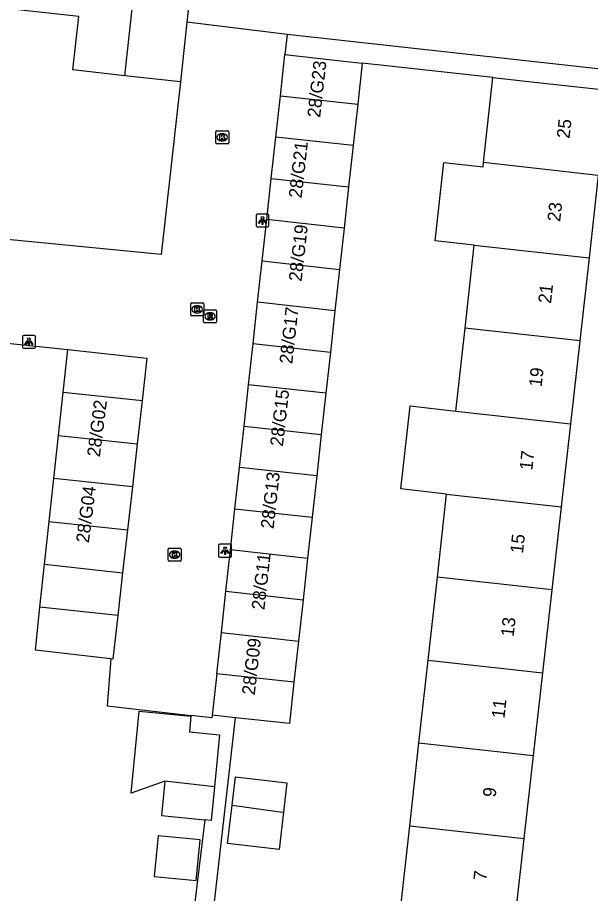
# Model space of a CAD drawing. Extents: x 162026 to 163499, y 387297 to 388169.
# Drawn here: x 162203.9 to 162248.1, y 387569 to 387636.4 of the extents above; entities that cross this region are included whole.
import ezdxf

# ---------------------------------------------------------------- set-up
doc = ezdxf.new("R2010")
doc.units = 0
for name, color, linetype in [('IMGEO_Kolk', 7, 'Continuous'), ('IMGEO_Lichtpunt', 7, 'Continuous'), ('IMGEO_Muur', 7, 'Continuous'), ('IMGEO_Pand', 7, 'Continuous'), ('IMGEO_Pand_nummerreeks', 7, 'Continuous'), ('IMGEO_Rijbaan_lokaal_open', 7, 'Continuous'), ('IMGEO_Rioolput', 7, 'Continuous'), ('IMGEO_Voetpad_open', 7, 'Continuous')]:
    doc.layers.add(name, color=color, linetype=linetype)

msp = doc.modelspace()

# ---------------------------------------------------------------- linework, layer by layer
at = {"layer": 'IMGEO_Kolk'}
for p, q in [((162219.264, 387627.682), (162220.116, 387627.682)), ((162219.189, 387626.756), (162219.189, 387627.608)), ((162219.677, 387627.462), (162219.702, 387627.462)), ((162220.19, 387627.608), (162220.19, 387626.756)), ((162220.116, 387626.682), (162219.264, 387626.682)), ((162219.7, 387626.902), (162219.675, 387626.902)), ((162217.264, 387613.502), (162217.264, 387614.354)), ((162217.339, 387614.428), (162218.191, 387614.428)), ((162217.752, 387614.208), (162217.777, 387614.208)), ((162218.265, 387614.354), (162218.265, 387613.502)), ((162217.775, 387613.648), (162217.75, 387613.648)), ((162218.191, 387613.428), (162217.339, 387613.428)), ((162215.53, 387594.615), (162215.53, 387595.467)), ((162215.605, 387595.541), (162216.457, 387595.541)), ((162216.018, 387595.321), (162216.043, 387595.321)), ((162216.531, 387595.467), (162216.531, 387594.615)), ((162216.041, 387594.761), (162216.016, 387594.761)), ((162216.457, 387594.541), (162215.605, 387594.541))]:
    msp.add_line(p, q, dxfattribs=at)
for points in [[(162219.264, 387627.682), (162220.116, 387627.682)], [(162219.189, 387626.756), (162219.189, 387627.608)], [(162219.51, 387627.382), (162219.633, 387627.382), (162219.633, 387627.231), (162219.763, 387627.382), (162219.927, 387627.382), (162219.781, 387627.231), (162219.934, 387626.982), (162219.782, 387626.982), (162219.697, 387627.146), (162219.633, 387627.079), (162219.633, 387626.982), (162219.51, 387626.982), (162219.51, 387627.382)], [(162220.19, 387627.608), (162220.19, 387626.756)], [(162220.116, 387626.682), (162219.264, 387626.682)], [(162217.264, 387613.502), (162217.264, 387614.354)], [(162217.339, 387614.428), (162218.191, 387614.428)], [(162218.265, 387614.354), (162218.265, 387613.502)], [(162217.585, 387614.128), (162217.708, 387614.128), (162217.708, 387613.977), (162217.838, 387614.128), (162218.002, 387614.128), (162217.856, 387613.977), (162218.009, 387613.728), (162217.857, 387613.728), (162217.772, 387613.892), (162217.708, 387613.825), (162217.708, 387613.728), (162217.585, 387613.728), (162217.585, 387614.128)], [(162218.191, 387613.428), (162217.339, 387613.428)], [(162215.53, 387594.615), (162215.53, 387595.467)], [(162215.605, 387595.541), (162216.457, 387595.541)], [(162216.531, 387595.467), (162216.531, 387594.615)], [(162215.851, 387595.241), (162215.974, 387595.241), (162215.974, 387595.09), (162216.104, 387595.241), (162216.268, 387595.241), (162216.122, 387595.09), (162216.275, 387594.841), (162216.123, 387594.841), (162216.038, 387595.005), (162215.974, 387594.938), (162215.974, 387594.841), (162215.851, 387594.841), (162215.851, 387595.241)], [(162216.457, 387594.541), (162215.605, 387594.541)]]:
    msp.add_lwpolyline(points, dxfattribs=at)
for centre, start, end in [((162219.266, 387627.606), 91.55205, 178.44795), ((162219.266, 387627.606), 91.55205, 178.44795), ((162220.114, 387627.606), 1.55205, 88.44795), ((162220.114, 387627.606), 1.55205, 88.44795), ((162219.266, 387626.758), 181.55205, 268.44795), ((162219.266, 387626.758), 181.55205, 268.44795), ((162220.114, 387626.758), 271.55205, 358.44795), ((162220.114, 387626.758), 271.55205, 358.44795), ((162217.341, 387614.352), 91.55205, 178.44795), ((162217.341, 387614.352), 91.55205, 178.44795), ((162218.189, 387614.352), 1.55205, 88.44795), ((162218.189, 387614.352), 1.55205, 88.44795), ((162217.341, 387613.504), 181.55205, 268.44795), ((162217.341, 387613.504), 181.55205, 268.44795), ((162218.189, 387613.504), 271.55205, 358.44795), ((162218.189, 387613.504), 271.55205, 358.44795), ((162215.607, 387595.465), 91.55205, 178.44795), ((162215.607, 387595.465), 91.55205, 178.44795), ((162216.455, 387595.465), 1.55205, 88.44795), ((162216.455, 387595.465), 1.55205, 88.44795), ((162215.607, 387594.617), 181.55205, 268.44795), ((162215.607, 387594.617), 181.55205, 268.44795), ((162216.455, 387594.617), 271.55205, 358.44795), ((162216.455, 387594.617), 271.55205, 358.44795)]:
    msp.add_arc(centre, 0.0765, start, end, dxfattribs=at)
for centre, major_axis, ratio, start_param, end_param in [((162219.676, 387627.182), (-0.387, 0.002), 0.722429, 4.712389, 7.853982), ((162219.701, 387627.182), (-0.39, 0.002), 0.717154, 1.570796, 4.712389), ((162217.751, 387613.928), (-0.387, 0.002), 0.722429, 4.712389, 7.853982), ((162217.776, 387613.928), (-0.39, 0.002), 0.717154, 1.570796, 4.712389), ((162216.017, 387595.041), (-0.387, 0.002), 0.722429, 4.712389, 7.853982), ((162216.042, 387595.041), (-0.39, 0.002), 0.717154, 1.570796, 4.712389)]:
    msp.add_ellipse(centre, major_axis=major_axis, ratio=ratio, start_param=start_param, end_param=end_param, dxfattribs=at)
at = {"layer": 'IMGEO_Lichtpunt'}
for p, q in [((162222.296, 387621.175), (162222.296, 387620.368)), ((162222.296, 387621.175), (162222.296, 387620.368)), ((162223.198, 387621.27), (162222.39, 387621.27)), ((162223.198, 387621.27), (162222.39, 387621.27)), ((162223.292, 387620.368), (162223.292, 387621.175)), ((162223.292, 387620.368), (162223.292, 387621.175)), ((162222.39, 387620.274), (162223.198, 387620.274)), ((162222.39, 387620.274), (162223.198, 387620.274)), ((162204.309, 387611.835), (162204.309, 387611.028)), ((162204.309, 387611.835), (162204.309, 387611.028)), ((162205.211, 387611.93), (162204.403, 387611.93)), ((162205.211, 387611.93), (162204.403, 387611.93)), ((162205.305, 387611.028), (162205.305, 387611.835)), ((162205.305, 387611.028), (162205.305, 387611.835)), ((162204.403, 387610.934), (162205.211, 387610.934)), ((162204.403, 387610.934), (162205.211, 387610.934)), ((162219.411, 387595.757), (162219.411, 387594.95)), ((162219.411, 387595.757), (162219.411, 387594.95)), ((162220.313, 387595.852), (162219.505, 387595.852)), ((162220.313, 387595.852), (162219.505, 387595.852)), ((162220.407, 387594.95), (162220.407, 387595.757)), ((162220.407, 387594.95), (162220.407, 387595.757)), ((162219.505, 387594.856), (162220.313, 387594.856)), ((162219.505, 387594.856), (162220.313, 387594.856))]:
    msp.add_line(p, q, dxfattribs=at)
for points in [[(162222.67, 387620.839), (162222.709, 387620.811), (162222.521, 387620.549), (162222.483, 387620.576), (162222.67, 387620.839)], [(162222.772, 387620.791), (162222.819, 387620.791), (162222.819, 387620.469), (162222.772, 387620.469), (162222.772, 387620.791)], [(162222.882, 387620.811), (162222.92, 387620.838), (162223.107, 387620.576), (162223.068, 387620.548), (162222.882, 387620.811)], [(162204.683, 387611.499), (162204.722, 387611.471), (162204.534, 387611.209), (162204.496, 387611.236), (162204.683, 387611.499)], [(162204.895, 387611.471), (162204.933, 387611.498), (162205.12, 387611.236), (162205.081, 387611.208), (162204.895, 387611.471)], [(162204.785, 387611.451), (162204.832, 387611.451), (162204.832, 387611.129), (162204.785, 387611.129), (162204.785, 387611.451)], [(162219.785, 387595.421), (162219.824, 387595.393), (162219.636, 387595.131), (162219.598, 387595.158), (162219.785, 387595.421)], [(162219.887, 387595.373), (162219.934, 387595.373), (162219.934, 387595.051), (162219.887, 387595.051), (162219.887, 387595.373)], [(162219.997, 387595.393), (162220.035, 387595.42), (162220.222, 387595.158), (162220.183, 387595.13), (162219.997, 387595.393)]]:
    msp.add_lwpolyline(points, dxfattribs=at)
for centre in [(162222.795, 387620.973), (162204.808, 387611.633), (162219.91, 387595.555)]:
    msp.add_circle(centre, 0.0994, dxfattribs=at)
for centre, start, end in [((162222.39, 387621.175), 90, 180), ((162222.39, 387621.175), 90, 180), ((162223.198, 387621.175), 0, 90), ((162223.198, 387621.175), 0, 90), ((162222.39, 387620.368), 180, 270), ((162222.39, 387620.368), 180, 270), ((162223.198, 387620.368), 270, 0), ((162223.198, 387620.368), 270, 360), ((162204.403, 387611.835), 90, 180), ((162204.403, 387611.835), 90, 180), ((162205.211, 387611.835), 0, 90), ((162205.211, 387611.835), 0, 90), ((162204.403, 387611.028), 180, 270), ((162204.403, 387611.028), 180, 270), ((162205.211, 387611.028), 270, 0), ((162205.211, 387611.028), 270, 360), ((162219.505, 387595.757), 90, 180), ((162219.505, 387595.757), 90, 180), ((162220.313, 387595.757), 0, 90), ((162220.313, 387595.757), 0, 90), ((162219.505, 387594.95), 180, 270), ((162219.505, 387594.95), 180, 270), ((162220.313, 387594.95), 270, 0), ((162220.313, 387594.95), 270, 360)]:
    msp.add_arc(centre, 0.0946, start, end, dxfattribs=at)
at = {"layer": 'IMGEO_Muur'}
msp.add_lwpolyline([(162185.674, 387611.291), (162189.153, 387612.794), (162207.795, 387610.848)], dxfattribs=at)
at = {"layer": 'IMGEO_Pand'}
for points in [[(162212.187, 387631.922), (162212.973, 387638.978)], [(162212.973, 387638.978), (162217.254, 387638.502), (162216.98, 387636.035)], [(162212.187, 387631.922), (162208.185, 387632.367), (162208.641, 387636.467), (162202.796, 387637.117)], [(162216.98, 387636.035), (162216.469, 387631.445)], [(162224.169, 387630.377), (162224.519, 387633.556)], [(162224.519, 387633.556), (162229.488, 387632.992), (162230.472, 387632.88)], [(162230.472, 387632.88), (162230.124, 387629.722)], [(162216.469, 387631.445), (162212.187, 387631.922)], [(162239.812, 387625.23), (162240.54, 387631.778)], [(162240.54, 387631.778), (162244.422, 387631.347), (162249.391, 387630.796)], [(162223.82, 387627.198), (162224.169, 387630.377)], [(162224.169, 387630.377), (162230.124, 387629.722)], [(162230.124, 387629.722), (162229.773, 387626.543)], [(162223.47, 387624.018), (162223.82, 387627.198)], [(162229.773, 387626.543), (162223.82, 387627.198)], [(162229.773, 387626.543), (162229.422, 387623.364)], [(162239.105, 387618.87), (162236.083, 387619.207), (162236.755, 387625.24), (162239.776, 387624.903), (162239.812, 387625.23)], [(162248.656, 387624.246), (162239.812, 387625.23)], [(162223.121, 387620.839), (162223.47, 387624.018)], [(162223.47, 387624.018), (162229.422, 387623.364)], [(162248.656, 387624.246), (162247.942, 387617.886)], [(162229.422, 387623.364), (162229.071, 387620.185)], [(162222.771, 387617.66), (162223.121, 387620.839)], [(162229.071, 387620.185), (162223.121, 387620.839)], [(162229.071, 387620.185), (162228.72, 387617.006)], [(162238.394, 387612.479), (162239.105, 387618.87)], [(162239.105, 387618.87), (162247.942, 387617.886)], [(162222.422, 387614.48), (162222.771, 387617.66)], [(162222.771, 387617.66), (162228.72, 387617.006)], [(162247.942, 387617.886), (162247.225, 387611.496)], [(162228.72, 387617.006), (162228.37, 387613.827)], [(162222.072, 387611.301), (162222.422, 387614.48)], [(162228.37, 387613.827), (162222.422, 387614.48)], [(162228.37, 387613.827), (162228.019, 387610.647)], [(162237.685, 387606.098), (162238.394, 387612.479)], [(162247.225, 387611.496), (162238.394, 387612.479)], [(162247.225, 387611.496), (162246.509, 387605.116)], [(162207.439, 387607.538), (162207.795, 387610.848)], [(162207.795, 387610.848), (162213.89, 387610.18), (162213.518, 387606.885)], [(162221.722, 387608.122), (162222.072, 387611.301)], [(162222.072, 387611.301), (162228.019, 387610.647)], [(162228.019, 387610.647), (162227.668, 387607.468)], [(162221.373, 387604.943), (162221.722, 387608.122)], [(162227.668, 387607.468), (162221.722, 387608.122)], [(162207.083, 387604.229), (162207.439, 387607.538)], [(162213.518, 387606.885), (162207.439, 387607.538)], [(162227.668, 387607.468), (162227.317, 387604.289)], [(162213.518, 387606.885), (162213.144, 387603.577)], [(162236.974, 387599.708), (162233.45, 387600.1), (162234.133, 387606.237), (162234.161, 387606.49), (162237.685, 387606.098)], [(162237.685, 387606.098), (162246.509, 387605.116)], [(162221.023, 387601.764), (162221.373, 387604.943)], [(162221.373, 387604.943), (162227.317, 387604.289)], [(162246.509, 387605.116), (162245.792, 387598.726)], [(162206.727, 387600.919), (162207.083, 387604.229)], [(162207.083, 387604.229), (162213.144, 387603.577)], [(162227.317, 387604.289), (162226.966, 387601.11)], [(162213.144, 387603.577), (162212.771, 387600.269)], [(162220.674, 387598.584), (162221.023, 387601.764)], [(162226.966, 387601.11), (162221.023, 387601.764)], [(162206.372, 387597.609), (162206.727, 387600.919)], [(162212.771, 387600.269), (162206.727, 387600.919)], [(162226.966, 387601.11), (162226.616, 387597.931)], [(162212.771, 387600.269), (162212.397, 387596.961)], [(162236.264, 387593.317), (162236.974, 387599.708)], [(162236.974, 387599.708), (162245.792, 387598.726)], [(162245.792, 387598.726), (162245.075, 387592.336)], [(162220.324, 387595.405), (162220.674, 387598.584)], [(162220.674, 387598.584), (162226.616, 387597.931)], [(162206.016, 387594.299), (162206.372, 387597.609)], [(162206.372, 387597.609), (162212.397, 387596.961)], [(162226.616, 387597.931), (162226.265, 387594.752)], [(162212.397, 387596.961), (162212.024, 387593.653)], [(162219.975, 387592.226), (162220.324, 387595.405)], [(162226.265, 387594.752), (162220.324, 387595.405)], [(162226.265, 387594.752), (162225.914, 387591.573)], [(162205.66, 387590.99), (162206.016, 387594.299)], [(162206.016, 387594.299), (162212.024, 387593.653)], [(162212.024, 387593.653), (162211.65, 387590.346)], [(162235.554, 387586.926), (162236.264, 387593.317)], [(162245.075, 387592.336), (162236.264, 387593.317)], [(162219.625, 387589.046), (162219.975, 387592.226)], [(162219.975, 387592.226), (162225.914, 387591.573)], [(162245.075, 387592.336), (162244.358, 387585.947)], [(162225.914, 387591.573), (162225.563, 387588.394)], [(162211.127, 387587.022), (162205.304, 387587.68), (162205.66, 387590.99)], [(162211.65, 387590.346), (162205.66, 387590.99)], [(162211.65, 387590.346), (162211.273, 387587.006), (162211.127, 387587.022)], [(162219.276, 387585.867), (162219.625, 387589.046)], [(162219.625, 387589.046), (162225.563, 387588.394)], [(162225.563, 387588.394), (162225.212, 387585.214)], [(162234.844, 387580.545), (162235.554, 387586.926)], [(162235.554, 387586.926), (162244.358, 387585.947)], [(162219.276, 387585.867), (162218.926, 387582.688)], [(162225.212, 387585.214), (162219.276, 387585.867)], [(162244.358, 387585.947), (162243.642, 387579.567)], [(162225.212, 387585.214), (162224.861, 387582.031), (162223.896, 387582.138), (162220.71, 387582.491)], [(162215.281, 387577.595), (162212.679, 387576.674), (162213.296, 387582.99), (162217.277, 387582.6)], [(162217.277, 387582.6), (162217.161, 387581.407), (162219.48, 387581.179), (162219.086, 387577.164)], [(162220.71, 387582.491), (162218.926, 387582.688)], [(162234.136, 387574.175), (162234.844, 387580.545)], [(162234.844, 387580.545), (162243.642, 387579.567)], [(162243.642, 387579.567), (162242.927, 387573.197)], [(162220.457, 387575.761), (162220.714, 387577.945), (162224.672, 387577.479), (162224.406, 387575.221)], [(162215.281, 387577.595), (162215.021, 387574.957), (162218.354, 387574.629)], [(162219.086, 387577.164), (162215.281, 387577.595)], [(162219.086, 387577.164), (162218.832, 387574.582), (162218.354, 387574.629)], [(162224.406, 387575.221), (162224.067, 387572.335), (162220.109, 387572.801), (162220.457, 387575.761)], [(162220.457, 387575.761), (162223.957, 387575.269), (162224.406, 387575.221)], [(162233.446, 387567.963), (162234.136, 387574.175)], [(162234.136, 387574.175), (162242.927, 387573.197)], [(162214.462, 387570.263), (162217.675, 387569.947), (162217.984, 387573.089), (162214.772, 387573.405), (162214.462, 387570.263)], [(162242.927, 387573.197), (162242.23, 387566.986)]]:
    msp.add_lwpolyline(points, dxfattribs=at)
at = {"layer": 'IMGEO_Rijbaan_lokaal_open'}
for points in [[(162224.692, 387635.082), (162216.98, 387636.035)], [(162224.692, 387635.082), (162224.519, 387633.556)], [(162216.469, 387631.445), (162214.989, 387618.142), (162195.255, 387620.087)], [(162185.674, 387611.291), (162189.153, 387612.794), (162207.795, 387610.848)], [(162211.127, 387587.022), (162210.842, 387583.401), (162217.284, 387582.658)], [(162218.926, 387582.688), (162218.894, 387582.472), (162217.284, 387582.658)]]:
    msp.add_lwpolyline(points, dxfattribs=at)
at = {"layer": 'IMGEO_Rioolput'}
for p, q in [((162218.26, 387612.969), (162218.26, 387613.821)), ((162218.335, 387613.895), (162219.187, 387613.895)), ((162218.748, 387613.675), (162218.773, 387613.675)), ((162219.261, 387613.821), (162219.261, 387612.969)), ((162219.187, 387612.895), (162218.335, 387612.895)), ((162218.771, 387613.115), (162218.746, 387613.115))]:
    msp.add_line(p, q, dxfattribs=at)
for points in [[(162218.26, 387612.969), (162218.26, 387613.821)], [(162218.335, 387613.895), (162219.187, 387613.895)], [(162218.849, 387613.593), (162218.597, 387613.595), (162218.597, 387613.195)], [(162218.775, 387613.514), (162218.721, 387613.514), (162218.721, 387613.433)], [(162219.261, 387613.821), (162219.261, 387612.969)], [(162219.187, 387612.895), (162218.335, 387612.895)], [(162218.597, 387613.195), (162218.721, 387613.195), (162218.721, 387613.357), (162218.732, 387613.357)], [(162218.721, 387613.433), (162218.773, 387613.433)], [(162218.779, 387613.328), (162218.85, 387613.195), (162218.99, 387613.195), (162218.925, 387613.321)]]:
    msp.add_lwpolyline(points, dxfattribs=at)
for centre, radius, start, end in [((162218.337, 387613.819), 0.0765, 91.55205, 178.44795), ((162218.337, 387613.819), 0.0765, 91.55205, 178.44795), ((162218.781, 387613.418), 0.0964, 77.00612, 93.18647), ((162218.795, 387613.475), 0.0378, 276.66336, 79.67722), ((162218.848, 387613.483), 0.109, 350.36119, 89.41601), ((162219.185, 387613.819), 0.0765, 1.55205, 88.44795), ((162219.185, 387613.819), 0.0765, 1.55205, 88.44795), ((162218.337, 387612.971), 0.0765, 181.55205, 268.44795), ((162218.337, 387612.971), 0.0765, 181.55205, 268.44795), ((162218.731, 387613.304), 0.0533, 26.02933, 88.69889), ((162218.757, 387613.622), 0.19, 274.7715, 282.96867), ((162218.846, 387613.483), 0.112, 277.58423, 350.98172), ((162218.83, 387613.268), 0.108, 29.51342, 73.79051), ((162219.185, 387612.971), 0.0765, 271.55205, 358.44795), ((162219.185, 387612.971), 0.0765, 271.55205, 358.44795)]:
    msp.add_arc(centre, radius, start, end, dxfattribs=at)
for centre, major_axis, ratio, start_param, end_param in [((162218.747, 387613.395), (-0.387, 0.002), 0.722429, 4.712389, 7.853982), ((162218.772, 387613.395), (-0.39, 0.002), 0.717154, 1.570796, 4.712389)]:
    msp.add_ellipse(centre, major_axis=major_axis, ratio=ratio, start_param=start_param, end_param=end_param, dxfattribs=at)
at = {"layer": 'IMGEO_Voetpad_open'}
for points in [[(162255.366, 387631.702), (162224.692, 387635.082)], [(162240.54, 387631.778), (162230.472, 387632.88)], [(162245.725, 387545.476), (162217.006, 387548.268), (162216.81, 387548.287), (162216.94, 387549.426), (162220.71, 387582.491)], [(162217.284, 387582.658), (162217.277, 387582.6)], [(162218.354, 387574.629), (162217.015, 387563.648)]]:
    msp.add_lwpolyline(points, dxfattribs=at)

# ---------------------------------------------------------------- texts
at = {"layer": 'IMGEO_Pand_nummerreeks'}
for s, rotation, p in [('28/G23', 83.53482, (162227.232, 387628.657)), ('25', 83.59656, (162246.434, 387627.052)), ('28/G21', 83.52006, (162225.803, 387622.454)), ('23', 83.59454, (162245.715, 387620.644)), ('28/G19', 83.53482, (162225.802, 387616.042)), ('21', 83.59656, (162245.009, 387614.347)), ('28/G17', 83.53482, (162225.083, 387609.694)), ('19', 83.59656, (162244.287, 387607.916)), ('28/G15', 83.53482, (162224.363, 387603.343)), ('28/G02', 82.70305, (162210.266, 387602.529)), ('17', 83.59454, (162243.568, 387601.508)), ('28/G13', 83.53482, (162223.644, 387596.992)), ('28/G04', 82.70305, (162209.419, 387595.909)), ('15', 83.59656, (162242.848, 387595.099)), ('28/G11', 83.53482, (162222.936, 387590.751)), ('13', 83.59656, (162242.129, 387588.69)), ('28/G09', 83.53482, (162222.194, 387584.197)), ('11', 83.59656, (162241.423, 387582.395)), ('9', 83.59656, (162240.743, 387576.33)), ('7', 83.59656, (162240.023, 387569.922))]:
    msp.add_text(s, height=1, rotation=rotation, dxfattribs=at).set_placement(p)

doc.saveas('drawing.dxf')
